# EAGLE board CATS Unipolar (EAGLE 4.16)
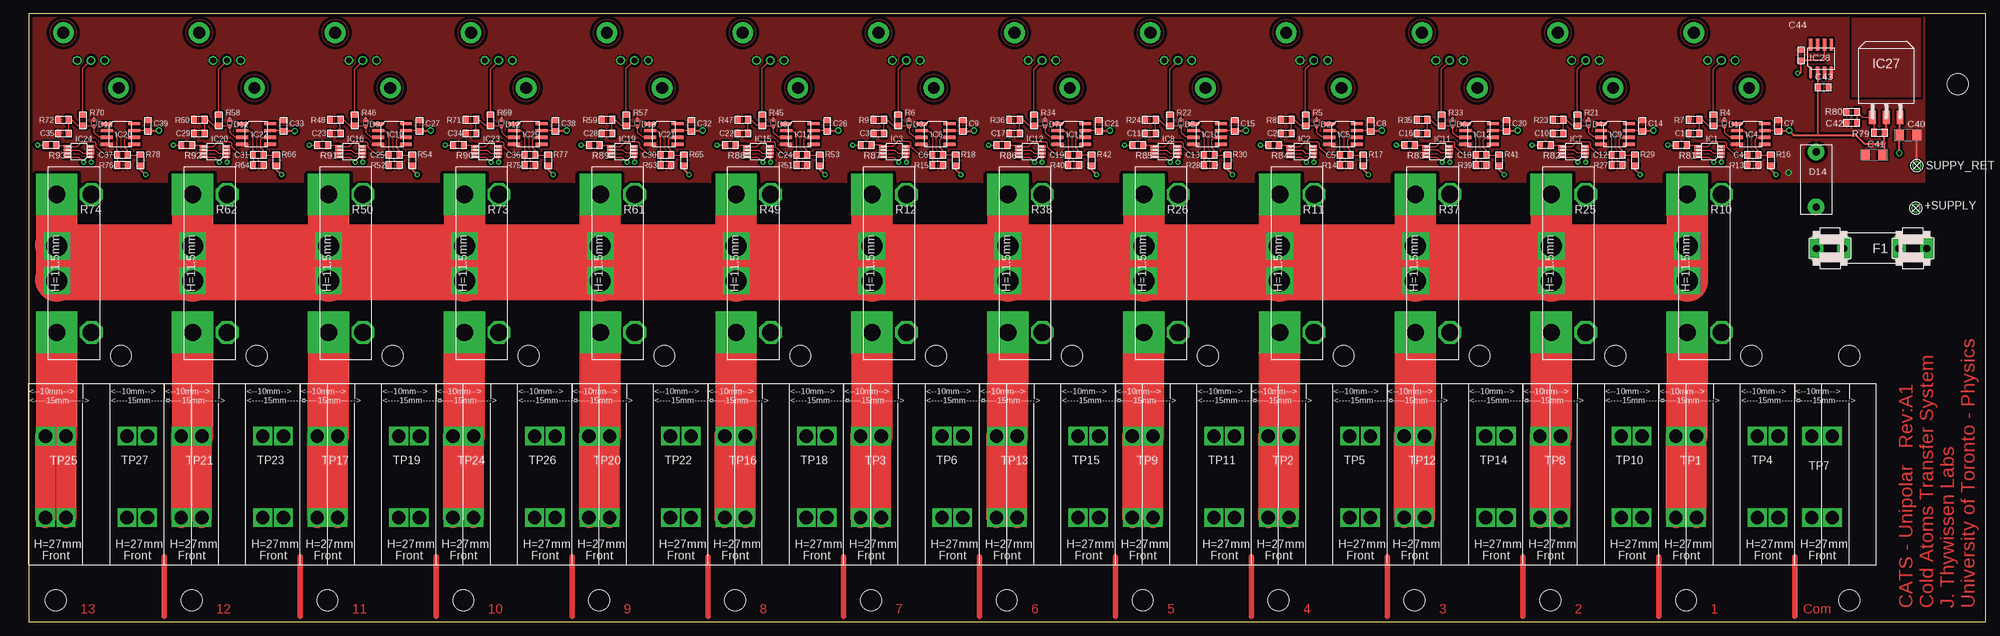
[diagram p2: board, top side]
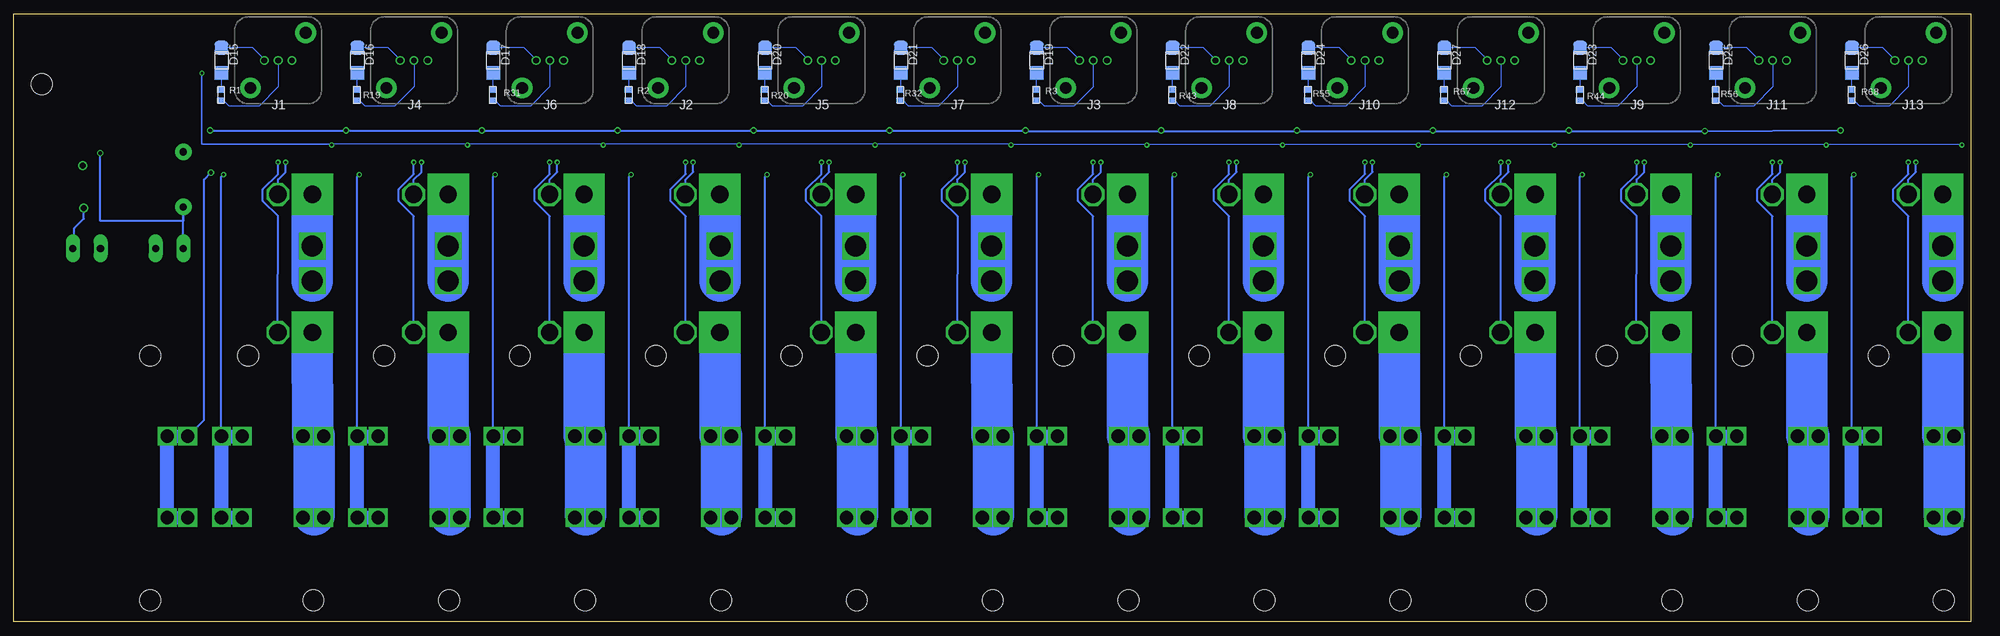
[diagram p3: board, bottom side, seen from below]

Size 360.16 x 112 mm. Coordinates in mm from the lower left corner, seen from the top.
Outline: 0,112 0,0 360.16,0 360.16,112 0,112
Copper layers (1*16): Top 0.035mm / dielectric 1.5mm / Bottom 0.035mm
Design rules "DRC standard check (7mil trace and gap, 20mil drill, etc)": minimum track width 7mil, minimum drill 20mil, track to track 7mil, track to pad 7mil, pad to pad 7mil, via to via 7mil, smd to smd 7mil, copper to edge 25mil, drill to drill 8mil, minimum pad ring 10mil, minimum via ring 8mil, stop-mask expansion 4mil, vias tented up to drill 0mil, thermal gap 10mil
Net classes: 0 default: clearance 0.406 mm; 1 Power: width 1.27 mm, drill 0.178 mm, clearance 3.175 mm
Holes 3.86 mm at 5,4 30,4 55,4 80,4 105,4 130,4 155,4 180,4 205,4 230,4 255,4 280,4 305,4 335,4 355,99 17,49 42,49 67,49 92,49 117,49 142,49 167,49 192,49 217,49 242,49 267,49 292,49 317,49 335,49
bKeepout: area 1.5,0.5 to 8.5,7.5; area 26.5,0.5 to 33.5,7.5; area 51.5,0.5 to 58.5,7.5; area 76.5,0.5 to 83.5,7.5; area 101.5,0.5 to 108.5,7.5; area 126.5,0.5 to 133.5,7.5; area 151.5,0.5 to 158.5,7.5; area 176.5,0.5 to 183.5,7.5; area 201.5,0.5 to 208.5,7.5; area 226.5,0.5 to 233.5,7.5; area 251.5,0.5 to 258.5,7.5; area 276.5,0.5 to 283.5,7.5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
tRestrict: 65 lines

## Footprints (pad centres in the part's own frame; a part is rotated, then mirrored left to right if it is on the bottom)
TP-0.042B = drill 1.067 round: TP 0,0
2012(0805) = smd 1.016 x 1.397: 1 -0.953,0; 2 0.953,0
EIA-A = smd 1.6 x 1.8: 1 -1.27,0; 2 1.905,0
SOD523 = smd 0.7 x 0.5: A 1.27,0; C 0,0
PASSIVE_0.4" = drill 1.321 pad 3.048 round: 1 -5.08,0; 2 5.08,0
1209 = smd 2.5 x 2.5: A 2.3,0; K -2.3,0
FUSE = drill 1.321 pad 2.54 long: 1A -10.16,0; 1B -5.08,0; 2A 10.16,0; 2B 5.08,0
MSOP8 = smd 0.4 x 1.2: 1 -0.635,-1.905; 2 0,-1.905; 3 0.635,-1.905; 4 1.27,-1.905; 5 1.27,2.54; 6 0.635,2.54; 7 0,2.54; 8 -0.635,2.54
SOIC-8 = smd 0.6 x 2.2: 1 -1.27,-2.54; 2 0,-2.54; 3 1.27,-2.54; 4 2.54,-2.54; 5 2.54,2.54; 6 1.27,2.54; 7 0,2.54; 8 -1.27,2.54
TO263 = smd 1.27 x 2.54: 1 -2.54,0; 2 0,0; 3 2.54,0
CONN-BNC-AMP-TYPE1VERT = drill 1.067 round: CONDUCTOR 0,0; SHIELD1 -2.54,0; SHIELD2 2.54,0 | drill 2.184 pad 3.81 round: MTG1 -5.08,-5.08; MTG2 5.08,5.08
OHMITE_650 = drill 3.175 pad 7.62 square: CURRENT1 -12.7,-3.81; CURRENT2 12.7,-3.81 | drill 3.175 octagon: SENSE1 -12.7,2.54; SENSE2 12.7,2.54
PHEONIX_ZFKDS-10/15MM-TERMINAL-BLOCK = drill 2.438 square: T@1 -1.9,-7.5; T@2 1.9,-7.5; T@3 1.9,7.5; T@4 -1.9,7.5

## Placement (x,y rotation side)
+SUPPLY  [TP-0.042B]  347.25,76.2 90 top
C1  10nF  [2012(0805)]  306.43,89.95 0 top
C2  10nF  [2012(0805)]  231.43,89.95 0 top
C3  10nF  [2012(0805)]  156.43,89.95 0 top
C4  100pF  [2012(0805)]  317.27,86.01 0 top
C5  100pF  [2012(0805)]  242.27,86.01 0 top
C6  100pF  [2012(0805)]  167.27,86.01 0 top
C7  0.1uF  [2012(0805)]  321.97,91.35 90 top
C8  0.1uF  [2012(0805)]  246.97,91.35 90 top
C9  0.1uF  [2012(0805)]  171.97,91.35 90 top
C10  10nF  [2012(0805)]  281.43,89.95 0 top
C11  10nF  [2012(0805)]  206.43,89.95 0 top
C12  100pF  [2012(0805)]  292.27,86.01 0 top
C13  100pF  [2012(0805)]  217.27,86.01 0 top
C14  0.1uF  [2012(0805)]  296.97,91.35 90 top
C15  0.1uF  [2012(0805)]  221.97,91.35 90 top
C16  10nF  [2012(0805)]  256.43,89.95 0 top
C17  10nF  [2012(0805)]  181.43,89.95 0 top
C18  100pF  [2012(0805)]  267.27,86.01 0 top
C19  100pF  [2012(0805)]  192.27,86.01 0 top
C20  0.1uF  [2012(0805)]  271.97,91.35 90 top
C21  0.1uF  [2012(0805)]  196.97,91.35 90 top
C22  10nF  [2012(0805)]  131.43,89.95 0 top
C23  10nF  [2012(0805)]  56.43,89.95 0 top
C24  100pF  [2012(0805)]  142.27,86.01 0 top
C25  100pF  [2012(0805)]  67.27,86.01 0 top
C26  0.1uF  [2012(0805)]  146.97,91.35 90 top
C27  0.1uF  [2012(0805)]  71.97,91.35 90 top
C28  10nF  [2012(0805)]  106.43,89.95 0 top
C29  10nF  [2012(0805)]  31.43,89.95 0 top
C30  100pF  [2012(0805)]  117.27,86.01 0 top
C31  100pF  [2012(0805)]  42.27,86.01 0 top
C32  0.1uF  [2012(0805)]  121.97,91.35 90 top
C33  0.1uF  [2012(0805)]  46.97,91.35 90 top
C34  10nF  [2012(0805)]  81.43,89.95 0 top
C35  10nF  [2012(0805)]  6.43,89.95 0 top
C36  100pF  [2012(0805)]  92.27,86.01 0 top
C37  100pF  [2012(0805)]  17.27,86.01 0 top
C38  0.1uF  [2012(0805)]  96.97,91.35 90 top
C39  0.1uF  [2012(0805)]  21.97,91.35 90 top
C40  100uF/35V  [EIA-A]  346.14,89.6 180 top
C41  100uF/35V  [EIA-A]  339.28,86.04 0 top
C42  0.1uF  [2012(0805)]  335.47,91.88 0 top
C43  0.1uF  [2012(0805)]  330.22,98.42 0 top
C44  0.1uF  [2012(0805)]  326.14,104.33 270 top
D1  1N4148WT  [SOD523]  312.02,91.22 90 top
D2  1N4148WT  [SOD523]  237.02,91.22 90 top
D3  1N4148WT  [SOD523]  162.02,91.22 90 top
D4  1N4148WT  [SOD523]  287.02,91.22 90 top
D5  1N4148WT  [SOD523]  212.02,91.22 90 top
D6  1N4148WT  [SOD523]  262.02,91.22 90 top
D7  1N4148WT  [SOD523]  187.02,91.22 90 top
D8  1N4148WT  [SOD523]  137.02,91.22 90 top
D9  1N4148WT  [SOD523]  62.02,91.22 90 top
D10  1N4148WT  [SOD523]  112.02,91.22 90 top
D11  1N4148WT  [SOD523]  37.02,91.22 90 top
D12  1N4148WT  [SOD523]  87.02,91.22 90 top
D13  1N4148WT  [SOD523]  12.02,91.22 90 top
D14  1N4750A  [PASSIVE_0.4"]  328.93,81.47 270 top
D15  SML-LXL1209UPGC  [1209]  321.9,103.4 270 bottom
D16  SML-LXL1209UPGC  [1209]  296.9,103.4 270 bottom
D17  SML-LXL1209UPGC  [1209]  271.9,103.4 270 bottom
D18  SML-LXL1209UPGC  [1209]  246.9,103.4 270 bottom
D19  SML-LXL1209UPGC  [1209]  171.9,103.4 270 bottom
D20  SML-LXL1209UPGC  [1209]  221.9,103.4 270 bottom
D21  SML-LXL1209UPGC  [1209]  196.9,103.4 270 bottom
D22  SML-LXL1209UPGC  [1209]  146.9,103.4 270 bottom
D23  SML-LXL1209UPGC  [1209]  71.9,103.4 270 bottom
D24  SML-LXL1209UPGC  [1209]  121.9,103.4 270 bottom
D25  SML-LXL1209UPGC  [1209]  46.9,103.4 270 bottom
D26  SML-LXL1209UPGC  [1209]  21.9,103.4 270 bottom
D27  SML-LXL1209UPGC  [1209]  96.9,103.4 270 bottom
F1  0.1A-5x20  [FUSE]  339.09,68.77 180 top
IC1  AD8212RMZ  [MSOP8]  309.61,86.27 90 top
IC2  AD8212RMZ  [MSOP8]  234.6,86.27 90 top
IC3  AD8212RMZ  [MSOP8]  159.6,86.27 90 top
IC4  AD820ARZ  [SOIC-8]  316.89,90.46 270 top
IC5  AD820ARZ  [SOIC-8]  241.89,90.46 270 top
IC6  AD820ARZ  [SOIC-8]  166.89,90.46 270 top
IC7  AD8212RMZ  [MSOP8]  284.61,86.27 90 top
IC8  AD8212RMZ  [MSOP8]  209.6,86.27 90 top
IC9  AD820ARZ  [SOIC-8]  291.89,90.46 270 top
IC10  AD820ARZ  [SOIC-8]  216.89,90.46 270 top
IC11  AD8212RMZ  [MSOP8]  259.61,86.27 90 top
IC12  AD8212RMZ  [MSOP8]  184.6,86.27 90 top
IC13  AD820ARZ  [SOIC-8]  266.89,90.46 270 top
IC14  AD820ARZ  [SOIC-8]  191.89,90.46 270 top
IC15  AD8212RMZ  [MSOP8]  134.6,86.27 90 top
IC16  AD8212RMZ  [MSOP8]  59.6,86.27 90 top
IC17  AD820ARZ  [SOIC-8]  141.89,90.46 270 top
IC18  AD820ARZ  [SOIC-8]  66.89,90.46 270 top
IC19  AD8212RMZ  [MSOP8]  109.61,86.27 90 top
IC20  AD8212RMZ  [MSOP8]  34.6,86.27 90 top
IC21  AD820ARZ  [SOIC-8]  116.89,90.46 270 top
IC22  AD820ARZ  [SOIC-8]  41.89,90.46 270 top
IC23  AD8212RMZ  [MSOP8]  84.61,86.27 90 top
IC24  AD8212RMZ  [MSOP8]  9.61,86.27 90 top
IC25  AD820ARZ  [SOIC-8]  91.89,90.46 270 top
IC26  AD820ARZ  [SOIC-8]  16.89,90.46 270 top
IC27  LM1086CS-ADJ  [TO263]  341.82,92.9 0 top
IC28  ADR435AR(Z)  [SOIC-8]  329.18,103.69 0 top
J1  Amp 227673-1  [CONN-BNC-AMP-TYPE1VERT]  311.49,103.38 0 bottom
J2  Amp 227673-1  [CONN-BNC-AMP-TYPE1VERT]  236.49,103.38 0 bottom
J3  Amp 227673-1  [CONN-BNC-AMP-TYPE1VERT]  161.49,103.38 0 bottom
J4  Amp 227673-1  [CONN-BNC-AMP-TYPE1VERT]  286.49,103.38 0 bottom
J5  Amp 227673-1  [CONN-BNC-AMP-TYPE1VERT]  211.49,103.38 0 bottom
J6  Amp 227673-1  [CONN-BNC-AMP-TYPE1VERT]  261.49,103.38 0 bottom
J7  Amp 227673-1  [CONN-BNC-AMP-TYPE1VERT]  186.49,103.38 0 bottom
J8  Amp 227673-1  [CONN-BNC-AMP-TYPE1VERT]  136.49,103.38 0 bottom
J9  Amp 227673-1  [CONN-BNC-AMP-TYPE1VERT]  61.49,103.38 0 bottom
J10  Amp 227673-1  [CONN-BNC-AMP-TYPE1VERT]  111.49,103.38 0 bottom
J11  Amp 227673-1  [CONN-BNC-AMP-TYPE1VERT]  36.49,103.38 0 bottom
J12  Amp 227673-1  [CONN-BNC-AMP-TYPE1VERT]  86.49,103.38 0 bottom
J13  Amp 227673-1  [CONN-BNC-AMP-TYPE1VERT]  11.49,103.38 0 bottom
R1  3.01K  [2012(0805)]  322,97 270 bottom
R2  3.01K  [2012(0805)]  247,97 270 bottom
R3  3.01K  [2012(0805)]  172,97 270 bottom
R4  9.09K  [2012(0805)]  309.99,92.36 270 top
R5  9.09K  [2012(0805)]  234.99,92.36 270 top
R6  9.09K  [2012(0805)]  159.99,92.36 270 top
R7  1K  [2012(0805)]  306.43,92.49 0 top
R8  1K  [2012(0805)]  231.43,92.49 0 top
R9  1K  [2012(0805)]  156.43,92.49 0 top
R10  2mOhm/5W  [OHMITE_650]  309,66 270 top
R11  2mOhm/5W  [OHMITE_650]  234,66 270 top
R12  2mOhm/5W  [OHMITE_650]  159,66 270 top
R13  3.92K  [2012(0805)]  317.27,84.11 180 top
R14  3.92K  [2012(0805)]  242.27,84.11 180 top
R15  3.92K  [2012(0805)]  167.27,84.11 180 top
R16  100  [2012(0805)]  320.57,85 270 top
R17  100  [2012(0805)]  245.57,85 270 top
R18  100  [2012(0805)]  170.57,85 270 top
R19  3.01K  [2012(0805)]  297,97 270 bottom
R20  3.01K  [2012(0805)]  222,97 270 bottom
R21  9.09K  [2012(0805)]  284.99,92.36 270 top
R22  9.09K  [2012(0805)]  209.99,92.36 270 top
R23  1K  [2012(0805)]  281.43,92.49 0 top
R24  1K  [2012(0805)]  206.43,92.49 0 top
R25  2mOhm/5W  [OHMITE_650]  284,66 270 top
R26  2mOhm/5W  [OHMITE_650]  209,66 270 top
R27  3.92K  [2012(0805)]  292.27,84.11 180 top
R28  3.92K  [2012(0805)]  217.27,84.11 180 top
R29  100  [2012(0805)]  295.57,85 270 top
R30  100  [2012(0805)]  220.57,85 270 top
R31  3.01K  [2012(0805)]  272,97 270 bottom
R32  3.01K  [2012(0805)]  197,97 270 bottom
R33  9.09K  [2012(0805)]  259.99,92.36 270 top
R34  9.09K  [2012(0805)]  184.99,92.36 270 top
R35  1K  [2012(0805)]  256.43,92.49 0 top
R36  1K  [2012(0805)]  181.43,92.49 0 top
R37  2mOhm/5W  [OHMITE_650]  259,66 270 top
R38  2mOhm/5W  [OHMITE_650]  184,66 270 top
R39  3.92K  [2012(0805)]  267.27,84.11 180 top
R40  3.92K  [2012(0805)]  192.27,84.11 180 top
R41  100  [2012(0805)]  270.57,85 270 top
R42  100  [2012(0805)]  195.57,85 270 top
R43  3.01K  [2012(0805)]  147,97 270 bottom
R44  3.01K  [2012(0805)]  72,97 270 bottom
R45  9.09K  [2012(0805)]  134.99,92.36 270 top
R46  9.09K  [2012(0805)]  59.99,92.36 270 top
R47  1K  [2012(0805)]  131.43,92.49 0 top
R48  1K  [2012(0805)]  56.43,92.49 0 top
R49  2mOhm/5W  [OHMITE_650]  134,66 270 top
R50  2mOhm/5W  [OHMITE_650]  59,66 270 top
R51  3.92K  [2012(0805)]  142.27,84.11 180 top
R52  3.92K  [2012(0805)]  67.27,84.11 180 top
R53  100  [2012(0805)]  145.57,85 270 top
R54  100  [2012(0805)]  70.57,85 270 top
R55  3.01K  [2012(0805)]  122,97 270 bottom
R56  3.01K  [2012(0805)]  47,97 270 bottom
R57  9.09K  [2012(0805)]  109.99,92.36 270 top
R58  9.09K  [2012(0805)]  34.99,92.36 270 top
R59  1K  [2012(0805)]  106.43,92.49 0 top
R60  1K  [2012(0805)]  31.43,92.49 0 top
R61  2mOhm/5W  [OHMITE_650]  109,66 270 top
R62  2mOhm/5W  [OHMITE_650]  34,66 270 top
R63  3.92K  [2012(0805)]  117.27,84.11 180 top
R64  3.92K  [2012(0805)]  42.27,84.11 180 top
R65  100  [2012(0805)]  120.57,85 270 top
R66  100  [2012(0805)]  45.57,85 270 top
R67  3.01K  [2012(0805)]  97,97 270 bottom
R68  3.01K  [2012(0805)]  22,97 270 bottom
R69  9.09K  [2012(0805)]  84.99,92.36 270 top
R70  9.09K  [2012(0805)]  9.99,92.36 270 top
R71  1K  [2012(0805)]  81.43,92.49 0 top
R72  1K  [2012(0805)]  6.43,92.49 0 top
R73  2mOhm/5W  [OHMITE_650]  84,66 270 top
R74  2mOhm/5W  [OHMITE_650]  9,66 270 top
R75  3.92K  [2012(0805)]  92.27,84.11 180 top
R76  3.92K  [2012(0805)]  17.27,84.11 180 top
R77  100  [2012(0805)]  95.57,85 270 top
R78  100  [2012(0805)]  20.57,85 270 top
R79  124  [2012(0805)]  340.55,90.11 0 top
R80  1.47K  [2012(0805)]  335.47,93.92 0 top
R81  75K  [2012(0805)]  304.12,87.76 180 top
R82  75K  [2012(0805)]  279.12,87.76 180 top
R83  75K  [2012(0805)]  254.12,87.76 180 top
R84  75K  [2012(0805)]  229.12,87.76 180 top
R85  75K  [2012(0805)]  204.12,87.76 180 top
R86  75K  [2012(0805)]  179.12,87.76 180 top
R87  75K  [2012(0805)]  154.12,87.76 180 top
R88  75K  [2012(0805)]  129.12,87.76 180 top
R89  75K  [2012(0805)]  104.12,87.76 180 top
R90  75K  [2012(0805)]  79.12,87.76 180 top
R91  75K  [2012(0805)]  54.12,87.76 180 top
R92  75K  [2012(0805)]  29.12,87.76 180 top
R93  75K  [2012(0805)]  4.12,87.76 180 top
SUPPY_RET  [TP-0.042B]  347.44,84.01 270 top
TP1  Pheonix-1987631  [PHEONIX_ZFKDS-10/15MM-TERMINAL-BLOCK]  305,26.7 0 top
TP2  Pheonix-1987631  [PHEONIX_ZFKDS-10/15MM-TERMINAL-BLOCK]  230,26.7 0 top
TP3  Pheonix-1987631  [PHEONIX_ZFKDS-10/15MM-TERMINAL-BLOCK]  155,26.7 0 top
TP4  Pheonix-1987628  [PHEONIX_ZFKDS-10/15MM-TERMINAL-BLOCK]  320,26.7 0 top
TP5  Pheonix-1987628  [PHEONIX_ZFKDS-10/15MM-TERMINAL-BLOCK]  245,26.7 0 top
TP6  Pheonix-1987628  [PHEONIX_ZFKDS-10/15MM-TERMINAL-BLOCK]  170,26.7 0 top
TP7  Pheonix-1987628  [PHEONIX_ZFKDS-10/15MM-TERMINAL-BLOCK]  330,26.7 0 top
TP8  Pheonix-1987631  [PHEONIX_ZFKDS-10/15MM-TERMINAL-BLOCK]  280,26.7 0 top
TP9  Pheonix-1987631  [PHEONIX_ZFKDS-10/15MM-TERMINAL-BLOCK]  205,26.7 0 top
TP10  Pheonix-1987628  [PHEONIX_ZFKDS-10/15MM-TERMINAL-BLOCK]  295,26.7 0 top
TP11  Pheonix-1987628  [PHEONIX_ZFKDS-10/15MM-TERMINAL-BLOCK]  220,26.7 0 top
TP12  Pheonix-1987631  [PHEONIX_ZFKDS-10/15MM-TERMINAL-BLOCK]  255,26.7 0 top
TP13  Pheonix-1987631  [PHEONIX_ZFKDS-10/15MM-TERMINAL-BLOCK]  180,26.7 0 top
TP14  Pheonix-1987628  [PHEONIX_ZFKDS-10/15MM-TERMINAL-BLOCK]  270,26.7 0 top
TP15  Pheonix-1987628  [PHEONIX_ZFKDS-10/15MM-TERMINAL-BLOCK]  195,26.7 0 top
TP16  Pheonix-1987631  [PHEONIX_ZFKDS-10/15MM-TERMINAL-BLOCK]  130,26.7 0 top
TP17  Pheonix-1987631  [PHEONIX_ZFKDS-10/15MM-TERMINAL-BLOCK]  55,26.7 0 top
TP18  Pheonix-1987628  [PHEONIX_ZFKDS-10/15MM-TERMINAL-BLOCK]  145,26.7 0 top
TP19  Pheonix-1987628  [PHEONIX_ZFKDS-10/15MM-TERMINAL-BLOCK]  70,26.7 0 top
TP20  Pheonix-1987631  [PHEONIX_ZFKDS-10/15MM-TERMINAL-BLOCK]  105,26.7 0 top
TP21  Pheonix-1987631  [PHEONIX_ZFKDS-10/15MM-TERMINAL-BLOCK]  30,26.7 0 top
TP22  Pheonix-1987628  [PHEONIX_ZFKDS-10/15MM-TERMINAL-BLOCK]  120,26.7 0 top
TP23  Pheonix-1987628  [PHEONIX_ZFKDS-10/15MM-TERMINAL-BLOCK]  45,26.7 0 top
TP24  Pheonix-1987631  [PHEONIX_ZFKDS-10/15MM-TERMINAL-BLOCK]  80,26.7 0 top
TP25  Pheonix-1987631  [PHEONIX_ZFKDS-10/15MM-TERMINAL-BLOCK]  5,26.7 0 top
TP26  Pheonix-1987628  [PHEONIX_ZFKDS-10/15MM-TERMINAL-BLOCK]  95,26.7 0 top
TP27  Pheonix-1987628  [PHEONIX_ZFKDS-10/15MM-TERMINAL-BLOCK]  20,26.7 0 top
U$106  [TITLEBLOCK_PCB]  not placed on the board

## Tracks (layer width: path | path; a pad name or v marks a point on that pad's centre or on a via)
+5.0V  (via drill 0.51)
  Top 0.178: R93.2 3.17,87.82 v1.65,87.82 | v26.65,87.82 26.65,87.75 R92.2 | v51.65,87.82 51.65,87.75 R91.2 | v76.65,87.82 76.65,87.75 R90.2 | v101.65,87.82 101.65,87.75 R89.2 | v126.65,87.82 126.65,87.75 R88.2 | v151.65,87.82 151.65,87.75 R87.2 | v176.65,87.82 176.65,87.75 R86.2 | v201.65,87.82 201.65,87.75 R85.2 | v226.65,87.82 226.65,87.75 R84.2 | v251.65,87.82 251.65,87.75 R83.2 | v276.65,87.82 276.65,87.75 R82.2 | v301.65,87.82 301.65,87.75 R81.2
  Top 0.254: 326.14,103.44 C44.2 | IC28.6 330.45,103.44 326.14,103.44 | v325.5,101.03 326.14,101.03 326.14,103.44
  Bottom 0.178: 276.65,88 v276.65,87.82 | v301.65,87.82 301.65,88 276.65,88 | 251.65,88 v251.65,87.82 | 251.65,88 276.65,88 | 226.65,88 v226.65,87.82 | 226.65,88 251.65,88 | 201.65,88 v201.65,87.82 | 201.65,88 226.65,88 | v176.65,87.82 176.65,88 | 176.65,88 201.65,88 | 151.65,88 v151.65,87.82 | 176.65,88 151.65,88 | 126.65,88 v126.65,87.82 | 151.65,88 126.65,88 | 101.65,88 v101.65,87.82 | 126.65,88 101.65,88 | 76.65,88 v76.65,87.82 | 101.65,88 76.65,88 | 51.65,88 v51.65,87.82 | 76.65,88 51.65,88 | 26.65,88 v26.65,87.82 | 51.65,88 26.65,88 | 1.65,88 1.5,88 | 1.65,88 v1.65,87.82 | 26.65,88 1.65,88
  Bottom 0.254: v325.5,101.03 325.5,87.95 301.62,87.95 301.62,88 301.65,88
+16V  (via drill 0.71)
  Top 0.178: C39.1 22.05,90.39 22.05,90.33 21.92,90.46 IC26.7 | C33.1 47.05,90.39 47.05,90.33 46.92,90.46 IC22.7 | C27.1 72.05,90.39 72.05,90.33 71.92,90.46 IC18.7 | C38.1 97.05,90.39 97.05,90.33 96.92,90.46 IC25.7 | C32.1 122.05,90.39 122.05,90.33 121.92,90.46 IC21.7 | C26.1 147.05,90.39 147.05,90.33 146.92,90.46 IC17.7 | C9.1 172.05,90.39 172.05,90.33 171.92,90.46 IC6.7 | C21.1 197.05,90.39 197.05,90.33 196.92,90.46 IC14.7 | C15.1 222.05,90.39 222.05,90.33 221.92,90.46 IC10.7 | C8.1 247.05,90.39 247.05,90.33 246.92,90.46 IC5.7 | C20.1 272.05,90.39 272.05,90.33 271.92,90.46 IC13.7 | C14.1 297.05,90.39 297.05,90.33 296.92,90.46 IC9.7 | C7.1 322.05,90.39 322.05,90.33 321.92,90.46 IC4.7
  Top 0.254: 329.18,98.42 329.18,98.36 | 329.18,98.42 C43.1 329.27,89.6 329.31,89.6 | 329.18,98.42 IC28.2
  Top 0.381: 22.05,90.39 24,90.39 v24,90.5 | v49,90.39 47.05,90.39 | 72.05,90.39 74,90.39 v74,90.5 | 97.05,90.39 99,90.39 v99,90.5 | 122.05,90.39 124,90.39 v124,90.5 | 147.05,90.39 149,90.39 v149,90.5 | 172.05,90.39 174,90.39 v174,90.5 | 197.05,90.39 199,90.39 v199,90.5 | 222.05,90.39 224,90.39 v224,90.5 | 247.05,90.39 249,90.39 v249,90.5 | 272.05,90.39 274,90.39 v274,90.5 | 297.05,90.39 299,90.39 v299,90.5 | 324,90.39 322.05,90.39 | v324,90.5 324,90.39 | IC27.2 341.82,90.11 R79.2 341.5,88.07 | 341.5,88.07 341.5,86.04 C41.2 | 324,90.39 324.8,89.6 329.31,89.6 336.23,89.6 337.76,88.07 341.5,88.07 | 341.5,88.07 341.57,88.07
  Bottom 0.254: 49,90.37 v49,90.39
  Bottom 0.381: 49,90.37 v24,90.5 | 74,90.39 v49,90.39 | 74,90.39 v74,90.5 | 99,90.39 74,90.39 | 99,90.39 v99,90.5 | 124,90.39 99,90.39 | 124,90.39 v124,90.5 | 149,90.39 124,90.39 | 149,90.39 v149,90.5 | 174,90.39 149,90.39 | v174,90.5 174,90.39 | 174,90.39 199,90.39 | 199,90.39 v199,90.5 | 199,90.39 224,90.39 | 224,90.39 v224,90.5 | 224,90.39 249,90.39 | 249,90.39 v249,90.5 | 249,90.39 274,90.39 | 274,90.39 v274,90.5 | 274,90.39 299,90.39 | 299,90.39 v299,90.5 | 299,90.39 324,90.39 v324,90.5
  pour Top (isolate 0.508): 335.47,111.14 335.47,96.71 348.17,96.71 348.17,111.14
+V-COIL  (via drill 3.86)
  Top 2: 5,69.4 5,69.3 5.2,64.1
  Top 7.62: R74.CURRENT1 v5.2,69.2 5.2,64.1 v5.2,62.8 5,63 30,63 | 55,63 30,63 | 80,63 55,63 | 105,63 80,63 | 130,63 105,63 | 155,63 130,63 | 180,63 155,63 | 180,63 205,63 | 205,63 230,63 | 230,63 255,63 | 255,63 280,63 | 280,63 305,63 v305.2,62.8 v305.2,69.2 R10.CURRENT1 | 30,63 v30.2,62.8 v30.2,69.2 R62.CURRENT1 | 55,63 v55.2,62.8 v55.2,69.2 R50.CURRENT1 | 80,63 v80.2,62.8 v80.2,69.2 R73.CURRENT1 | 105,63 v105.2,62.8 v105.2,69.2 R61.CURRENT1 | 130,63 v130.2,62.8 v130.2,69.2 R49.CURRENT1 | 155,63 v155.2,62.8 v155.2,69.2 R12.CURRENT1 | 180,63 v180.2,62.8 v180.2,69.2 R38.CURRENT1 | 205,63 v205.2,62.8 v205.2,69.2 R26.CURRENT1 | 230,63 v230.2,62.8 v230.2,69.2 R11.CURRENT1 | 255,63 v255.2,62.8 v255.2,69.2 R37.CURRENT1 | 280,63 v280.2,62.8 v280.2,69.2 R25.CURRENT1 | 5,69.4 305,69.4
  Bottom 7.62: v5.2,62.8 v5.2,69.2 R74.CURRENT1 | R62.CURRENT1 v30.2,69.2 v30.2,62.8 | R50.CURRENT1 v55.2,69.2 v55.2,62.8 | R73.CURRENT1 v80.2,69.2 v80.2,62.8 | R61.CURRENT1 v105.2,69.2 v105.2,62.8 | R49.CURRENT1 v130.2,69.2 v130.2,62.8 | R12.CURRENT1 v155.2,69.2 v155.2,62.8 | R38.CURRENT1 v180.2,69.2 v180.2,62.8 | R26.CURRENT1 v205.2,69.2 v205.2,62.8 | R11.CURRENT1 v230.2,69.2 v230.2,62.8 | R37.CURRENT1 v255.2,69.2 v255.2,62.8 | R25.CURRENT1 v280.2,69.2 v280.2,62.8 | R10.CURRENT1 v305.2,69.2 v305.2,62.8
AGND  (via drill 0.71)
  Top 0.36: C40.1 347.44,89.56 SUPPY_RET.TP
  Bottom 0.18: J13.SHIELD1 14.03,103.5 14,103.5 16.2,105.7 D26.K | J11.SHIELD1 39.03,103.5 39,103.5 41.2,105.7 D25.K | J9.SHIELD1 64.03,103.5 64,103.5 66.2,105.7 D23.K | J12.SHIELD1 89.03,103.5 89,103.5 91.2,105.7 D27.K | J10.SHIELD1 114.03,103.5 114,103.5 116.2,105.7 D24.K | J8.SHIELD1 139.03,103.5 139,103.5 141.2,105.7 D22.K | J3.SHIELD1 164.03,103.5 164,103.5 166.2,105.7 D19.K | J7.SHIELD1 189.03,103.5 189,103.5 191.2,105.7 D21.K | J5.SHIELD1 214.03,103.5 214,103.5 216.2,105.7 D20.K | J2.SHIELD1 239.03,103.5 239,103.5 241.2,105.7 D18.K | J6.SHIELD1 264.03,103.5 264,103.5 266.2,105.7 D17.K | J4.SHIELD1 289.03,103.5 289,103.5 291.2,105.7 D16.K | J1.SHIELD1 314.03,103.5 314,103.5 316.2,105.7 D15.K
  Bottom 0.381: TP7.T@4 325.12,37.18 325.12,81.47 v323.85,82.74
  Bottom 2.54: TP7.T@1 331.85,19.11 TP7.T@2 331.85,34.23 TP7.T@3 328.17,34.23 TP7.T@4
  pour Top (isolate 0.178, rank 2): 0,112 0,81 349,81 349,112
N$1
  Top 0.18: J13.CONDUCTOR 11.49,103.5 11.5,103.5 9.99,101.99 R70.1
  Bottom 0.18: R68.2 21.55,96.05 20.5,95 15,95 11.5,98.5 11.5,103.5 11.49,103.5 J13.CONDUCTOR
N$2
  Top 0.178: 7.45,89.95 C35.2 R72.2 7.95,92.49 8.97,91.47 9.86,91.47 9.99,91.35 R70.2 11.7,91.41 12.02,91.09 | 12.02,91.09 D13.C | 12.02,91.09 12.02,90.2 12.91,89.31 14.3,89.31 14.43,89.19 IC26.3
N$3  (via drill 0.51)
  Top 0.178: v11.51,84.62 IC24.1
  Bottom 0.381: R74.SENSE2 11.51,74.71 14.3,77.5 14.3,79.66 11.51,82.46 v11.51,84.62
N$4  (via drill 0.51)
  Top 0.178: v10.11,84.62 9.22,85.5 7.32,85.5 7.19,85.63 IC24.8
  Bottom 0.381: R74.SENSE1 11.51,81.44 10.11,82.84 v10.11,84.62
N$5
  Top 0.178: IC24.6 9.35,86.9 9.99,86.27 IC24.2
N$6
  Top 0.178: R76.2 16.32,86 16.34,86.01 | 14.43,90.33 14.3,90.46 IC26.2 14.43,90.46 14.3,90.33 15.7,90.33 16.34,89.7 16.34,86.01 | 16.34,86.01 C37.1 14.05,86.01 12.78,87.16 12.4,87.54 12.4,88.17 12.14,88.43 9.86,88.43 8.97,87.54 IC24.5 7.07,87.69 5.07,87.69 R93.1
N$7
  Top 0.178: 19.51,89.19 IC26.6 18.11,89.19 17.73,88.81 17.73,87.28 18.22,86.79 C37.2 18.11,86.01 18.18,85.95 R78.1
N$8
  Top 3.81: 6.81,34.2 TP25.T@3 | TP25.T@2 6.9,34.11 6.81,34.2 | TP25.T@4 3.1,34.32 3.13,34.32 3.1,34.3 TP25.T@4 | TP25.T@1 TP25.T@4 | TP25.T@4 3.1,34.07 3.13,34.07 3.25,34.2 6.81,34.2
  Top 7.62: R74.CURRENT2 5.16,34.32
  Bottom 2.54: 5.29,34.45 5.16,34.45 | 4.87,34.23 5.07,34.23 5.29,34.45 | 5.29,34.45 5.03,34.2 6.81,34.2 TP25.T@3
  Bottom 7.62: R74.CURRENT2 5.16,34.45 5.16,34.32 | 4.87,34.23 4.87,19.71
N$9
  Top 0.18: J11.CONDUCTOR 36.49,103.25 36.5,103.25 34.99,101.74 34.99,94.75 R58.1
  Bottom 0.18: R56.2 46.55,96.05 45.5,95 40,95 36.5,98.5 36.5,103 36.49,103 J11.CONDUCTOR
N$10  (via drill 0.51)
  Top 0.254: R78.2 20.57,83.3 v21.54,82.33
  Bottom 0.254: TP27.T@2 21.8,19.2 21.8,19.21 21.79,19.2 | TP27.T@3 21.8,34.2 21.9,34.09 | TP27.T@3 21.54,34.2 21.42,34.07 21.29,34.2 | 21.92,34.07 21.9,34.07 TP27.T@3
  Bottom 0.381: v21.54,82.33 21.92,81.95 21.92,34.07
  Bottom 2.54: TP27.T@1 21.79,19.2 | TP27.T@2 21.9,34.09 | 21.29,34.2 TP27.T@4
N$11
  Top 0.178: 32.45,89.95 C29.2 R60.2 32.95,92.49 33.97,91.47 34.86,91.47 34.99,91.35 R58.2 36.7,91.41 37.02,91.09 | 37.02,91.09 D11.C | 37.02,91.09 37.02,90.2 37.91,89.31 39.3,89.31 39.43,89.19 IC22.3
N$12  (via drill 0.51)
  Top 0.178: v36.51,84.62 IC20.1
  Bottom 0.381: R62.SENSE2 36.51,74.71 39.3,77.5 39.3,79.66 36.51,82.46 v36.51,84.62
N$13  (via drill 0.51)
  Top 0.178: v35.11,84.62 34.22,85.5 32.32,85.5 32.19,85.63 IC20.8
  Bottom 0.381: R62.SENSE1 36.51,81.44 35.11,82.84 v35.11,84.62
N$14
  Top 0.178: IC20.6 34.35,86.9 34.99,86.27 IC20.2
N$15
  Top 0.178: R64.2 41.32,86 41.34,86.01 | 39.43,90.33 39.3,90.46 IC22.2 39.43,90.46 39.3,90.33 40.7,90.33 41.34,89.7 41.34,86.01 | 41.34,86.01 C31.1 39.05,86.01 37.78,87.16 37.4,87.54 37.4,88.17 37.15,88.43 34.86,88.43 33.97,87.54 IC20.5 32.06,87.82 30.07,87.82 R92.1
N$16
  Top 0.178: 44.51,89.19 IC22.6 43.11,89.19 42.73,88.81 42.73,87.28 43.22,86.79 C31.2 43.11,86.01 43.18,85.95 R66.1
N$17
  Top 3.81: 31.81,34.2 TP21.T@3 | TP21.T@2 31.9,34.11 31.81,34.2 | TP21.T@4 28.1,34.32 28.13,34.32 28.1,34.3 TP21.T@4 | TP21.T@1 TP21.T@4 | TP21.T@4 28.1,34.07 28.13,34.07 28.25,34.2 31.81,34.2
  Top 7.62: R62.CURRENT2 30.16,34.32
  Bottom 2.54: 30.29,34.45 30.16,34.45 | 29.87,34.23 30.07,34.23 30.29,34.45 | 30.29,34.45 30.03,34.2 31.81,34.2 TP21.T@3
  Bottom 7.62: R62.CURRENT2 30.16,34.45 30.16,34.32 | 29.87,34.23 29.87,19.71
N$18  (via drill 0.51)
  Top 0.254: R66.2 45.57,83.3 v46.54,82.33
  Bottom 0.254: TP23.T@2 46.8,19.2 46.8,19.21 46.79,19.2 | TP23.T@3 46.8,34.2 46.9,34.09 | TP23.T@3 46.54,34.2 46.42,34.07 46.29,34.2 | 46.92,34.07 46.9,34.07 TP23.T@3
  Bottom 0.381: v46.54,82.33 46.92,81.95 46.92,34.07
  Bottom 2.54: TP23.T@1 46.79,19.2 | TP23.T@2 46.9,34.09 | 46.29,34.2 TP23.T@4
N$19
  Top 0.18: J9.CONDUCTOR 61.49,103.25 61.5,103.25 59.99,101.74 59.99,94.75 R46.1
  Bottom 0.18: R44.2 71.55,96.05 70.5,95 65,95 61.5,98.5 61.5,103 61.49,103 J9.CONDUCTOR
N$20
  Top 0.178: 57.45,89.95 C23.2 R48.2 57.95,92.49 58.97,91.47 59.86,91.47 59.99,91.35 R46.2 61.7,91.41 62.02,91.09 | 62.02,91.09 D9.C | 62.02,91.09 62.02,90.2 62.91,89.31 64.3,89.31 64.43,89.19 IC18.3
N$21  (via drill 0.51)
  Top 0.178: v61.51,84.62 IC16.1
  Bottom 0.381: R50.SENSE2 61.51,74.71 64.3,77.5 64.3,79.66 61.51,82.46 v61.51,84.62
N$22  (via drill 0.51)
  Top 0.178: v60.11,84.62 59.22,85.5 57.32,85.5 57.19,85.63 IC16.8
  Bottom 0.381: R50.SENSE1 61.51,81.44 60.11,82.84 v60.11,84.62
N$23
  Top 0.178: IC16.6 59.35,86.9 59.99,86.27 IC16.2
N$24
  Top 0.178: R52.2 66.32,86 66.34,86.01 | 64.43,90.33 64.3,90.46 IC18.2 64.43,90.46 64.3,90.33 65.7,90.33 66.34,89.7 66.34,86.01 | 66.34,86.01 C25.1 64.05,86.01 62.78,87.16 62.4,87.54 62.4,88.17 62.15,88.43 59.86,88.43 58.97,87.54 IC16.5 57.06,87.82 55.07,87.82 R91.1
N$25
  Top 0.178: 69.51,89.19 IC18.6 68.11,89.19 67.73,88.81 67.73,87.28 68.22,86.79 C25.2 68.11,86.01 68.18,85.95 R54.1
N$26
  Top 3.81: 56.81,34.2 TP17.T@3 | TP17.T@2 56.9,34.11 56.81,34.2 | TP17.T@4 53.1,34.32 53.13,34.32 53.1,34.3 TP17.T@4 | TP17.T@1 TP17.T@4 | TP17.T@4 53.1,34.07 53.13,34.07 53.26,34.2 56.81,34.2
  Top 7.62: R50.CURRENT2 55.16,34.32
  Bottom 2.54: 55.29,34.45 55.16,34.45 | 54.87,34.23 55.07,34.23 55.29,34.45 | 55.29,34.45 55.03,34.2 56.81,34.2 TP17.T@3
  Bottom 7.62: R50.CURRENT2 55.16,34.45 55.16,34.32 | 54.87,34.23 54.87,19.71
N$27  (via drill 0.51)
  Top 0.254: R54.2 70.57,83.3 v71.54,82.33
  Bottom 0.254: TP19.T@2 71.8,19.2 71.8,19.21 71.79,19.2 | TP19.T@3 71.8,34.2 71.9,34.09 | TP19.T@3 71.54,34.2 71.42,34.07 71.29,34.2 | 71.92,34.07 71.9,34.07 TP19.T@3
  Bottom 0.381: v71.54,82.33 71.92,81.95 71.92,34.07
  Bottom 2.54: TP19.T@1 71.79,19.2 | TP19.T@2 71.9,34.09 | 71.29,34.2 TP19.T@4
N$28
  Top 0.18: J12.CONDUCTOR 86.49,103.25 86.5,103.25 84.99,101.74 84.99,94.75 R69.1
  Bottom 0.18: R67.2 96.55,96.05 95.5,95 90,95 86.5,98.5 86.5,103.5 86.49,103.5 J12.CONDUCTOR
N$29
  Top 0.178: 82.45,89.95 C34.2 R71.2 82.95,92.49 83.97,91.47 84.86,91.47 84.99,91.35 R69.2 86.7,91.41 87.02,91.09 | 87.02,91.09 D12.C | 87.02,91.09 87.02,90.2 87.91,89.31 89.3,89.31 89.43,89.19 IC25.3
N$30  (via drill 0.51)
  Top 0.178: v86.51,84.62 IC23.1
  Bottom 0.381: R73.SENSE2 86.51,74.71 89.3,77.5 89.3,79.66 86.51,82.46 v86.51,84.62
N$31  (via drill 0.51)
  Top 0.178: v85.11,84.62 84.22,85.5 82.32,85.5 82.19,85.63 IC23.8
  Bottom 0.381: R73.SENSE1 86.51,81.44 85.11,82.84 v85.11,84.62
N$32
  Top 0.178: IC23.6 84.35,86.9 84.99,86.27 IC23.2
N$33
  Top 0.178: R75.2 91.32,86 91.34,86.01 | 89.43,90.33 89.3,90.46 IC25.2 89.43,90.46 89.3,90.33 90.7,90.33 91.34,89.7 91.34,86.01 | 91.34,86.01 C36.1 89.05,86.01 87.78,87.16 87.4,87.54 87.4,88.17 87.14,88.43 84.86,88.43 83.97,87.54 IC23.5 82.06,87.82 80.07,87.82 R90.1
N$34
  Top 0.178: 94.51,89.19 IC25.6 93.11,89.19 92.73,88.81 92.73,87.28 93.22,86.79 C36.2 93.11,86.01 93.18,85.95 R77.1
N$35
  Top 3.81: 81.81,34.2 TP24.T@3 | TP24.T@2 81.9,34.11 81.81,34.2 | TP24.T@4 78.1,34.32 78.13,34.32 78.1,34.3 TP24.T@4 | TP24.T@1 TP24.T@4 | TP24.T@4 78.1,34.07 78.13,34.07 78.25,34.2 81.81,34.2
  Top 7.62: R73.CURRENT2 80.16,34.32
  Bottom 2.54: 80.29,34.45 80.16,34.45 | 79.87,34.23 80.07,34.23 80.29,34.45 | 80.29,34.45 80.03,34.2 81.81,34.2 TP24.T@3
  Bottom 7.62: R73.CURRENT2 80.16,34.45 80.16,34.32 | 79.87,34.23 79.87,19.71
N$36  (via drill 0.51)
  Top 0.254: R77.2 95.57,83.3 v96.54,82.33
  Bottom 0.254: TP26.T@2 96.8,19.2 96.8,19.21 96.79,19.2 | TP26.T@3 96.8,34.2 96.9,34.09 | TP26.T@3 96.54,34.2 96.42,34.07 96.29,34.2 | 96.92,34.07 96.9,34.07 TP26.T@3
  Bottom 0.381: v96.54,82.33 96.92,81.95 96.92,34.07
  Bottom 2.54: TP26.T@1 96.79,19.2 | TP26.T@2 96.9,34.09 | 96.29,34.2 TP26.T@4
N$37
  Top 0.18: J10.CONDUCTOR 111.49,103.5 111.5,103.5 109.99,101.99 109.99,94.75 R57.1
  Bottom 0.18: R55.2 121.55,96.05 120.5,95 115,95 111.5,98.5 111.5,103.5 111.49,103.5 J10.CONDUCTOR
N$38
  Top 0.178: 107.45,89.95 C28.2 R59.2 107.95,92.49 108.97,91.47 109.86,91.47 109.99,91.35 R57.2 111.7,91.41 112.02,91.09 | 112.02,91.09 D10.C | 112.02,91.09 112.02,90.2 112.91,89.31 114.3,89.31 114.43,89.19 IC21.3
N$39  (via drill 0.51)
  Top 0.178: v111.51,84.62 IC19.1
  Bottom 0.381: R61.SENSE2 111.51,74.71 114.3,77.5 114.3,79.66 111.51,82.46 v111.51,84.62
N$40  (via drill 0.51)
  Top 0.178: v110.11,84.62 109.22,85.5 107.32,85.5 107.19,85.63 IC19.8
  Bottom 0.381: R61.SENSE1 111.51,81.44 110.11,82.84 v110.11,84.62
N$41
  Top 0.178: IC19.6 109.35,86.9 109.99,86.27 IC19.2
N$42
  Top 0.178: R63.2 116.32,86 116.34,86.01 | 114.43,90.33 114.3,90.46 IC21.2 114.43,90.46 114.3,90.33 115.7,90.33 116.34,89.7 116.34,86.01 | 116.34,86.01 C30.1 114.05,86.01 112.78,87.16 112.4,87.54 112.4,88.17 112.14,88.43 109.86,88.43 108.97,87.54 IC19.5 107.06,87.82 105.07,87.82 R89.1
N$43
  Top 0.178: 119.51,89.19 IC21.6 118.11,89.19 117.73,88.81 117.73,87.28 118.22,86.79 C30.2 118.11,86.01 118.18,85.95 R65.1
N$44
  Top 3.81: 106.81,34.2 TP20.T@3 | TP20.T@2 106.9,34.11 106.81,34.2 | TP20.T@4 103.1,34.32 103.13,34.32 103.1,34.3 TP20.T@4 | TP20.T@1 TP20.T@4 | TP20.T@4 103.1,34.07 103.13,34.07 103.25,34.2 106.81,34.2
  Top 7.62: R61.CURRENT2 105.16,34.32
  Bottom 2.54: 105.29,34.45 105.16,34.45 | 104.87,34.23 105.07,34.23 105.29,34.45 | 105.29,34.45 105.03,34.2 106.81,34.2 TP20.T@3
  Bottom 7.62: R61.CURRENT2 105.16,34.45 105.16,34.32 | 104.87,34.23 104.87,19.71
N$45  (via drill 0.51)
  Top 0.254: R65.2 120.57,83.3 v121.54,82.33
  Bottom 0.254: TP22.T@2 121.8,19.2 121.8,19.21 121.79,19.2 | TP22.T@3 121.8,34.2 121.9,34.09 | TP22.T@3 121.54,34.2 121.42,34.07 121.29,34.2 | 121.92,34.07 121.9,34.07 TP22.T@3 | 121.92,81.95 v121.54,82.33
  Bottom 0.381: 121.92,34.07 121.92,81.95
  Bottom 2.54: TP22.T@1 121.79,19.2 | TP22.T@2 121.9,34.09 | 121.29,34.2 TP22.T@4
N$46
  Top 0.18: J8.CONDUCTOR 136.49,103.5 136.5,103.5 134.99,101.99 134.99,94.75 R45.1
  Bottom 0.18: R43.2 146.55,96.05 145.5,95 140,95 136.5,98.5 136.5,103.5 136.49,103.5 J8.CONDUCTOR
N$47
  Top 0.178: 132.45,89.95 C22.2 R47.2 132.95,92.49 133.97,91.47 134.86,91.47 134.99,91.35 R45.2 136.7,91.41 137.02,91.09 | 137.02,91.09 D8.C | 137.02,91.09 137.02,90.2 137.91,89.31 139.3,89.31 139.43,89.19 IC17.3
N$48  (via drill 0.51)
  Top 0.178: v136.51,84.62 IC15.1
  Bottom 0.381: R49.SENSE2 136.51,74.71 139.3,77.5 139.3,79.66 136.51,82.46 v136.51,84.62
N$49  (via drill 0.51)
  Top 0.178: v135.11,84.62 134.22,85.5 132.32,85.5 132.19,85.63 IC15.8
  Bottom 0.381: R49.SENSE1 136.51,81.44 135.11,82.84 v135.11,84.62
N$50
  Top 0.178: IC15.6 134.35,86.9 134.99,86.27 IC15.2
N$51
  Top 0.178: R51.2 141.32,86 141.34,86.01 | 139.43,90.33 139.3,90.46 IC17.2 139.43,90.46 139.3,90.33 140.7,90.33 141.34,89.7 141.34,86.01 | 141.34,86.01 C24.1 139.05,86.01 137.78,87.16 137.4,87.54 137.4,88.17 137.15,88.43 134.86,88.43 133.97,87.54 IC15.5 132.06,87.82 130.07,87.82 R88.1
N$52
  Top 0.178: 144.51,89.19 IC17.6 143.11,89.19 142.73,88.81 142.73,87.28 143.22,86.79 C24.2 143.11,86.01 143.18,85.95 R53.1
N$53
  Top 3.81: 131.81,34.2 TP16.T@3 | TP16.T@2 131.9,34.11 131.81,34.2 | TP16.T@4 128.1,34.32 128.13,34.32 128.1,34.3 TP16.T@4 | TP16.T@1 TP16.T@4 | TP16.T@4 128.1,34.07 128.13,34.07 128.25,34.2 131.81,34.2
  Top 7.62: R49.CURRENT2 130.16,34.32
  Bottom 2.54: 130.29,34.45 130.16,34.45 | 129.87,34.23 130.07,34.23 130.29,34.45 | 130.29,34.45 130.03,34.2 131.81,34.2 TP16.T@3
  Bottom 7.62: R49.CURRENT2 130.16,34.45 130.16,34.32 | 129.87,34.23 129.87,19.71
N$54  (via drill 0.51)
  Top 0.254: R53.2 145.57,83.3 v146.54,82.33
  Bottom 0.254: TP18.T@2 146.8,19.2 146.8,19.21 146.79,19.2 | TP18.T@3 146.8,34.2 146.9,34.09 | TP18.T@3 146.54,34.2 146.42,34.07 146.29,34.2 | 146.92,34.07 146.9,34.07 TP18.T@3 | 146.92,81.95 v146.54,82.33
  Bottom 0.381: 146.92,34.07 146.92,81.95
  Bottom 2.54: TP18.T@1 146.79,19.2 | TP18.T@2 146.9,34.09 | 146.29,34.2 TP18.T@4
N$55
  Top 0.18: J3.CONDUCTOR 161.49,103.25 161.5,103.25 159.99,101.74 159.99,94.75 R6.1
  Bottom 0.18: R3.2 171.55,96.05 170.5,95 165,95 161.5,98.5 161.5,103.5 161.49,103.5 J3.CONDUCTOR
N$56
  Top 0.178: 157.45,89.95 C3.2 R9.2 157.95,92.49 158.97,91.47 159.86,91.47 159.99,91.35 R6.2 161.7,91.41 162.02,91.09 | 162.02,91.09 D3.C | 162.02,91.09 162.02,90.2 162.91,89.31 164.3,89.31 164.43,89.19 IC6.3
N$57  (via drill 0.51)
  Top 0.178: v161.51,84.62 IC3.1
  Bottom 0.381: R12.SENSE2 161.51,74.71 164.3,77.5 164.3,79.66 161.51,82.46 v161.51,84.62
N$58  (via drill 0.51)
  Top 0.178: v160.11,84.62 159.22,85.5 157.32,85.5 157.19,85.63 IC3.8
  Bottom 0.381: R12.SENSE1 161.51,81.44 160.11,82.84 v160.11,84.62
N$59
  Top 0.178: IC3.6 159.35,86.9 159.99,86.27 IC3.2
N$60
  Top 0.178: R15.2 166.32,86 166.34,86.01 | 164.43,90.33 164.3,90.46 IC6.2 164.43,90.46 164.3,90.33 165.7,90.33 166.34,89.7 166.34,86.01 | 166.34,86.01 C6.1 164.05,86.01 162.78,87.16 162.4,87.54 162.4,88.17 162.15,88.43 159.86,88.43 158.97,87.54 IC3.5 157.06,87.82 155.07,87.82 R87.1
N$61
  Top 0.178: 169.51,89.19 IC6.6 168.11,89.19 167.73,88.81 167.73,87.28 168.22,86.79 C6.2 168.11,86.01 168.18,85.95 R18.1
N$62
  Top 3.81: 156.81,34.2 TP3.T@3 | TP3.T@2 156.9,34.11 156.81,34.2 | TP3.T@4 153.1,34.32 153.13,34.32 153.1,34.3 TP3.T@4 | TP3.T@1 TP3.T@4 | TP3.T@4 153.1,34.07 153.13,34.07 153.25,34.2 156.81,34.2
  Top 7.62: R12.CURRENT2 155.16,34.32
  Bottom 2.54: 155.29,34.45 155.16,34.45 | 154.87,34.23 155.07,34.23 155.29,34.45 | 155.29,34.45 155.03,34.2 156.81,34.2 TP3.T@3
  Bottom 7.62: R12.CURRENT2 155.16,34.45 155.16,34.32 | 154.87,34.23 154.87,19.71
N$63  (via drill 0.51)
  Top 0.254: R18.2 170.57,83.3 v171.54,82.33
  Bottom 0.254: TP6.T@2 171.8,19.2 171.8,19.21 171.79,19.2 | TP6.T@3 171.8,34.2 171.9,34.09 | TP6.T@3 171.54,34.2 171.42,34.07 171.29,34.2 | 171.92,34.07 171.9,34.07 TP6.T@3
  Bottom 0.381: v171.54,82.33 171.92,81.95 171.92,34.07
  Bottom 2.54: 171.79,19.2 TP6.T@1 | 171.9,34.09 TP6.T@2 | 171.29,34.2 TP6.T@4
N$64
  Top 0.18: J7.CONDUCTOR 186.49,103.25 186.5,103.25 184.99,101.74 184.99,94.75 R34.1
  Bottom 0.18: R32.2 196.55,96.05 195.5,95 190,95 186.5,98.5 186.5,103 186.49,103 J7.CONDUCTOR
N$65
  Top 0.178: 182.45,89.95 C17.2 R36.2 182.95,92.49 183.97,91.47 184.86,91.47 184.99,91.35 R34.2 186.7,91.41 187.02,91.09 | 187.02,91.09 D7.C | 187.02,91.09 187.02,90.2 187.91,89.31 189.3,89.31 189.43,89.19 IC14.3
N$66  (via drill 0.51)
  Top 0.178: v186.51,84.62 IC12.1
  Bottom 0.381: R38.SENSE2 186.51,74.71 189.3,77.5 189.3,79.66 186.51,82.46 v186.51,84.62
N$67  (via drill 0.51)
  Top 0.178: v185.11,84.62 184.22,85.5 182.32,85.5 182.19,85.63 IC12.8
  Bottom 0.381: R38.SENSE1 186.51,81.44 185.11,82.84 v185.11,84.62
N$68
  Top 0.178: IC12.6 184.35,86.9 184.99,86.27 IC12.2
N$69
  Top 0.178: R40.2 191.32,86 191.34,86.01 | 189.43,90.33 189.3,90.46 IC14.2 189.43,90.46 189.3,90.33 190.7,90.33 191.34,89.7 191.34,86.01 | 191.34,86.01 C19.1 189.05,86.01 187.78,87.16 187.4,87.54 187.4,88.17 187.15,88.43 184.86,88.43 183.97,87.54 IC12.5 182.06,87.82 180.07,87.82 R86.1
N$70
  Top 0.178: 194.51,89.19 IC14.6 193.11,89.19 192.73,88.81 192.73,87.28 193.22,86.79 C19.2 193.11,86.01 193.18,85.95 R42.1
N$71
  Top 3.81: 181.81,34.2 TP13.T@3 | TP13.T@2 181.9,34.11 181.81,34.2 | TP13.T@4 178.1,34.32 178.13,34.32 178.1,34.3 TP13.T@4 | TP13.T@1 TP13.T@4 | TP13.T@4 178.1,34.07 178.13,34.07 178.25,34.2 181.81,34.2
  Top 7.62: R38.CURRENT2 180.16,34.32
  Bottom 2.54: 180.29,34.45 180.16,34.45 | 179.87,34.23 180.07,34.23 180.29,34.45 | 180.29,34.45 180.03,34.2 181.81,34.2 TP13.T@3
  Bottom 7.62: R38.CURRENT2 180.16,34.45 180.16,34.32 | 179.87,34.23 179.87,19.71
N$72  (via drill 0.51)
  Top 0.254: R42.2 195.57,83.3 v196.54,82.33
  Bottom 0.254: TP15.T@2 196.8,19.2 196.8,19.21 196.79,19.2 | TP15.T@3 196.8,34.2 196.9,34.09 | TP15.T@3 196.54,34.2 196.42,34.07 196.29,34.2 | 196.92,34.07 196.9,34.07 TP15.T@3
  Bottom 0.381: v196.54,82.33 196.92,81.95 196.92,34.07
  Bottom 2.54: 196.79,19.2 TP15.T@1 | 196.9,34.09 TP15.T@2 | 196.29,34.2 TP15.T@4
N$73
  Top 0.18: J5.CONDUCTOR 211.49,103.25 211.5,103.25 209.99,101.74 209.99,94.75 R22.1
  Bottom 0.18: R20.2 221.55,96.05 220.5,95 215,95 211.5,98.5 211.5,103.5 211.49,103.5 J5.CONDUCTOR
N$74
  Top 0.178: 207.45,89.95 C11.2 R24.2 207.95,92.49 208.97,91.47 209.86,91.47 209.99,91.35 R22.2 211.7,91.41 212.02,91.09 | 212.02,91.09 D5.C | 212.02,91.09 212.02,90.2 212.91,89.31 214.3,89.31 214.43,89.19 IC10.3
N$75  (via drill 0.51)
  Top 0.178: v211.51,84.62 IC8.1
  Bottom 0.381: R26.SENSE2 211.51,74.71 214.3,77.5 214.3,79.66 211.51,82.46 v211.51,84.62
N$76  (via drill 0.51)
  Top 0.178: v210.11,84.62 209.22,85.5 207.32,85.5 207.19,85.63 IC8.8
  Bottom 0.381: R26.SENSE1 211.51,81.44 210.11,82.84 v210.11,84.62
N$77
  Top 0.178: IC8.6 209.35,86.9 209.99,86.27 IC8.2
N$78
  Top 0.178: R28.2 216.32,86 216.34,86.01 | 214.43,90.33 214.3,90.46 IC10.2 214.43,90.46 214.3,90.33 215.7,90.33 216.34,89.7 216.34,86.01 | 216.34,86.01 C13.1 214.05,86.01 212.78,87.16 212.4,87.54 212.4,88.17 212.15,88.43 209.86,88.43 208.97,87.54 IC8.5 207.06,87.82 205.07,87.82 R85.1
N$79
  Top 0.178: 219.51,89.19 IC10.6 218.11,89.19 217.73,88.81 217.73,87.28 218.22,86.79 C13.2 218.11,86.01 218.18,85.95 R30.1
N$80
  Top 3.81: 206.81,34.2 TP9.T@3 | TP9.T@2 206.9,34.11 206.81,34.2 | TP9.T@4 203.1,34.32 203.13,34.32 203.1,34.3 TP9.T@4 | TP9.T@4 TP9.T@1 | TP9.T@4 203.1,34.07 203.13,34.07 203.25,34.2 206.81,34.2
  Top 7.62: R26.CURRENT2 205.16,34.32
  Bottom 2.54: 205.16,34.45 205.29,34.45 | 204.87,34.23 205.07,34.23 205.29,34.45 | 205.29,34.45 205.03,34.2 206.81,34.2 TP9.T@3
  Bottom 7.62: R26.CURRENT2 205.16,34.45 205.16,34.32 | 204.87,34.23 204.87,19.71
N$81  (via drill 0.51)
  Top 0.254: R30.2 220.57,83.3 v221.54,82.33
  Bottom 0.254: TP11.T@2 221.8,19.2 221.8,19.21 221.79,19.2 | TP11.T@3 221.8,34.2 221.9,34.09 | TP11.T@3 221.54,34.2 221.42,34.07 221.29,34.2 | 221.92,34.07 221.9,34.07 TP11.T@3
  Bottom 0.381: v221.54,82.33 221.92,81.95 221.92,34.07
  Bottom 2.54: 221.79,19.2 TP11.T@1 | 221.9,34.09 TP11.T@2 | 221.29,34.2 TP11.T@4
N$82
  Top 0.18: J2.CONDUCTOR 236.49,103.25 236.5,103.25 234.99,101.74 234.99,94.75 R5.1
  Bottom 0.18: R2.2 246.55,96.05 245.5,95 240,95 236.5,98.5 236.5,103.5 236.49,103.5 J2.CONDUCTOR
N$83
  Top 0.178: 232.45,89.95 C2.2 R8.2 232.95,92.49 233.97,91.47 234.86,91.47 234.99,91.35 R5.2 236.7,91.41 237.02,91.09 | 237.02,91.09 D2.C | 237.02,91.09 237.02,90.2 237.91,89.31 239.3,89.31 239.43,89.19 IC5.3
N$84  (via drill 0.51)
  Top 0.178: v236.51,84.62 IC2.1
  Bottom 0.381: R11.SENSE2 236.51,74.71 239.3,77.5 239.3,79.66 236.51,82.46 v236.51,84.62
N$85  (via drill 0.51)
  Top 0.178: v235.11,84.62 234.22,85.5 232.32,85.5 232.19,85.63 IC2.8
  Bottom 0.381: R11.SENSE1 236.51,81.44 235.11,82.84 v235.11,84.62
N$86
  Top 0.178: IC2.6 234.35,86.9 234.99,86.27 IC2.2
N$87
  Top 0.178: R14.2 241.32,86 241.34,86.01 | 239.43,90.33 239.3,90.46 IC5.2 239.43,90.46 239.3,90.33 240.7,90.33 241.34,89.7 241.34,86.01 | 241.34,86.01 C5.1 239.05,86.01 237.78,87.16 237.4,87.54 237.4,88.17 237.15,88.43 234.86,88.43 233.97,87.54 IC2.5 232.06,87.82 230.07,87.82 R84.1
N$88
  Top 0.178: 244.51,89.19 IC5.6 243.11,89.19 242.73,88.81 242.73,87.28 243.22,86.79 C5.2 243.11,86.01 243.18,85.95 R17.1
N$89
  Top 3.81: 231.81,34.2 TP2.T@3 | TP2.T@2 231.9,34.11 231.81,34.2 | TP2.T@4 228.1,34.32 228.13,34.32 228.1,34.3 TP2.T@4 | TP2.T@4 TP2.T@1 | TP2.T@4 228.1,34.07 228.13,34.07 228.25,34.2 231.81,34.2
  Top 7.62: R11.CURRENT2 230.16,34.32
  Bottom 2.54: 230.29,34.45 230.16,34.45 | 229.87,34.23 230.07,34.23 230.29,34.45 | 230.29,34.45 230.03,34.2 231.81,34.2 TP2.T@3
  Bottom 7.62: R11.CURRENT2 230.16,34.45 230.16,34.32 | 229.87,34.23 229.87,19.71
N$90  (via drill 0.51)
  Top 0.254: R17.2 245.57,83.3 v246.54,82.33
  Bottom 0.254: TP5.T@2 246.8,19.2 246.8,19.21 246.79,19.2 | TP5.T@3 246.8,34.2 246.9,34.09 | TP5.T@3 246.54,34.2 246.42,34.07 246.29,34.2 | 246.92,34.07 246.9,34.07 TP5.T@3
  Bottom 0.381: v246.54,82.33 246.92,81.95 246.92,34.07
  Bottom 2.54: TP5.T@1 246.79,19.2 | TP5.T@2 246.9,34.09 | 246.29,34.2 TP5.T@4
N$91
  Top 0.18: J6.CONDUCTOR 261.49,103.25 261.5,103.25 259.99,101.74 259.99,94.75 R33.1
  Bottom 0.18: R31.2 271.55,96.05 270.5,95 265,95 261.5,98.5 261.5,103.5 261.49,103.5 J6.CONDUCTOR
N$92
  Top 0.178: 257.45,89.95 C16.2 R35.2 257.95,92.49 258.97,91.47 259.86,91.47 259.99,91.35 R33.2 261.7,91.41 262.02,91.09 | 262.02,91.09 D6.C | 262.02,91.09 262.02,90.2 262.91,89.31 264.3,89.31 264.43,89.19 IC13.3
N$93  (via drill 0.51)
  Top 0.178: v261.51,84.62 IC11.1
  Bottom 0.381: R37.SENSE2 261.51,74.71 264.3,77.5 264.3,79.66 261.51,82.46 v261.51,84.62
N$94  (via drill 0.51)
  Top 0.178: v260.11,84.62 259.22,85.5 257.32,85.5 257.19,85.63 IC11.8
  Bottom 0.381: R37.SENSE1 261.51,81.44 260.11,82.84 v260.11,84.62
N$95
  Top 0.178: IC11.6 259.35,86.9 259.99,86.27 IC11.2
N$96
  Top 0.178: R39.2 266.32,86 266.34,86.01 | 264.43,90.33 264.3,90.46 IC13.2 264.43,90.46 264.3,90.33 265.7,90.33 266.34,89.7 266.34,86.01 | 266.34,86.01 C18.1 264.05,86.01 262.78,87.16 262.4,87.54 262.4,88.17 262.14,88.43 259.86,88.43 258.97,87.54 IC11.5 257.06,87.82 255.07,87.82 R83.1
N$97
  Top 0.178: 269.51,89.19 IC13.6 268.11,89.19 267.73,88.81 267.73,87.28 268.22,86.79 C18.2 268.11,86.01 268.18,85.95 R41.1
N$98
  Top 3.81: 256.81,34.2 TP12.T@3 | TP12.T@2 256.9,34.11 256.81,34.2 | TP12.T@4 253.1,34.32 253.13,34.32 253.1,34.3 TP12.T@4 | TP12.T@1 TP12.T@4 | TP12.T@4 253.1,34.07 253.13,34.07 253.25,34.2 256.81,34.2
  Top 7.62: R37.CURRENT2 255.16,34.32
  Bottom 2.54: 255.29,34.45 255.16,34.45 | 254.87,34.23 255.07,34.23 255.29,34.45 | 255.29,34.45 255.03,34.2 256.81,34.2 TP12.T@3
  Bottom 7.62: R37.CURRENT2 255.16,34.45 255.16,34.32 | 254.87,34.23 254.87,19.71
N$99  (via drill 0.51)
  Top 0.254: R41.2 270.57,83.3 v271.54,82.33
  Bottom 0.254: TP14.T@2 271.8,19.2 271.8,19.21 271.79,19.2 | TP14.T@3 271.8,34.2 271.9,34.09 | TP14.T@3 271.54,34.2 271.42,34.2 271.29,34.2 | 271.92,34.07 271.9,34.07 TP14.T@3
  Bottom 0.381: v271.54,82.33 271.92,81.95 271.92,34.07
  Bottom 2.54: TP14.T@1 271.79,19.2 | TP14.T@2 271.9,34.09 | 271.29,34.2 TP14.T@4
N$100
  Top 0.18: J4.CONDUCTOR 286.49,103.25 286.5,103.25 284.99,101.74 284.99,94.75 R21.1
  Bottom 0.18: R19.2 296.55,96.05 295.5,95 290,95 286.5,98.5 286.5,103.5 286.49,103.5 J4.CONDUCTOR
N$101
  Top 0.178: 282.45,89.95 C10.2 R23.2 282.95,92.49 283.97,91.47 284.86,91.47 284.99,91.35 R21.2 286.7,91.41 287.02,91.09 | 287.02,91.09 D4.C | 287.02,91.09 287.02,90.2 287.91,89.31 289.3,89.31 289.43,89.19 IC9.3
N$102  (via drill 0.51)
  Top 0.178: v286.51,84.62 IC7.1
  Bottom 0.381: R25.SENSE2 286.51,74.71 289.3,77.5 289.3,79.66 286.51,82.46 v286.51,84.62
N$103  (via drill 0.51)
  Top 0.178: v285.11,84.62 284.22,85.5 282.32,85.5 282.19,85.63 IC7.8
  Bottom 0.381: R25.SENSE1 286.51,81.44 285.11,82.84 v285.11,84.62
N$104
  Top 0.178: IC7.6 284.35,86.9 284.99,86.27 IC7.2
N$105
  Top 0.178: R27.2 291.32,86 291.34,86.01 | 289.43,90.33 289.3,90.46 IC9.2 289.43,90.46 289.3,90.33 290.7,90.33 291.34,89.7 291.34,86.01 | 291.34,86.01 C12.1 289.05,86.01 287.78,87.16 287.4,87.54 287.4,88.17 287.14,88.43 284.86,88.43 283.97,87.54 IC7.5 282.06,87.82 280.07,87.82 | 280.07,87.82 280.04,87.82 | R82.1 280.07,87.82
N$106
  Top 0.178: 294.51,89.19 IC9.6 293.11,89.19 292.73,88.81 292.73,87.28 293.22,86.79 C12.2 293.11,86.01 293.18,85.95 R29.1
N$107
  Top 3.81: 281.81,34.2 TP8.T@3 | TP8.T@2 281.9,34.11 281.81,34.2 | TP8.T@4 278.1,34.32 278.13,34.32 278.1,34.3 TP8.T@4 | TP8.T@1 TP8.T@4 | TP8.T@4 278.1,34.07 278.13,34.07 278.25,34.2 281.81,34.2
  Top 7.62: R25.CURRENT2 280.16,34.32
  Bottom 2.54: 280.29,34.45 280.16,34.45 | 279.87,34.23 280.07,34.23 280.29,34.45 | 280.29,34.45 280.03,34.2 281.81,34.2 TP8.T@3
  Bottom 7.62: R25.CURRENT2 280.16,34.45 280.16,34.32 | 279.87,34.23 279.87,19.71
N$108  (via drill 0.51)
  Top 0.254: R29.2 295.57,83.3 v296.54,82.33
  Bottom 0.254: TP10.T@2 296.8,19.2 296.8,19.21 296.79,19.2 | TP10.T@3 296.8,34.2 296.9,34.09 | TP10.T@3 296.54,34.2 296.42,34.2 296.29,34.2 | 296.92,34.07 296.9,34.07 TP10.T@3
  Bottom 0.381: v296.54,82.33 296.92,81.95 296.92,34.07
  Bottom 2.54: TP10.T@1 296.79,19.2 | TP10.T@2 296.9,34.09 | 296.29,34.2 TP10.T@4
N$109
  Top 0.18: J1.CONDUCTOR 311.49,103.25 311.5,103.25 309.99,101.74 309.99,94.75 R4.1
  Bottom 0.18: R1.2 322,96 321.5,96 320.5,95 315,95 311.5,98.5 311.5,103.5 311.49,103.5 J1.CONDUCTOR
N$110
  Top 0.178: 307.45,89.95 C1.2 R7.2 307.95,92.49 308.97,91.47 309.86,91.47 309.99,91.35 R4.2 311.7,91.41 312.02,91.09 | 312.02,91.09 D1.C | 312.02,91.09 312.02,90.2 312.91,89.31 314.3,89.31 314.43,89.19 IC4.3
N$111  (via drill 0.51)
  Top 0.178: v311.51,84.62 IC1.1
  Bottom 0.381: R10.SENSE2 311.51,74.71 314.3,77.5 314.3,79.66 311.51,82.46 v311.51,84.62
N$112  (via drill 0.51)
  Top 0.178: v310.11,84.62 309.22,85.5 307.32,85.5 307.19,85.63 IC1.8
  Bottom 0.381: R10.SENSE1 311.51,81.44 310.11,82.84 v310.11,84.62
N$113
  Top 0.178: IC1.6 309.35,86.9 309.99,86.27 IC1.2
N$114
  Top 0.178: R13.2 316.32,86 316.34,86.01 | 314.43,90.33 314.3,90.46 IC4.2 314.43,90.46 314.3,90.33 315.7,90.33 316.34,89.7 316.34,86.01 | 316.34,86.01 C4.1 314.05,86.01 312.78,87.16 312.4,87.54 312.4,88.17 312.14,88.43 309.86,88.43 308.97,87.54 IC1.5 307.06,87.82 305.07,87.82 | 305.07,87.82 304.93,87.82 | R81.1 305.07,87.82
N$115
  Top 0.178: 319.51,89.19 IC4.6 318.11,89.19 317.73,88.81 317.73,87.28 318.22,86.79 C4.2 318.11,86.01 318.18,85.95 R16.1
N$116
  Top 3.81: 306.81,34.2 TP1.T@3 | TP1.T@2 306.9,34.11 306.81,34.2 | TP1.T@4 303.1,34.32 303.13,34.32 303.1,34.3 TP1.T@4 | TP1.T@1 TP1.T@4 | TP1.T@4 303.1,34.07 303.13,34.07 303.25,34.2 306.81,34.2
  Top 7.62: R10.CURRENT2 305.16,34.32
  Bottom 2.54: 305.29,34.45 305.16,34.45 | 304.87,34.23 305.07,34.23 305.29,34.45 | 305.29,34.45 305.03,34.2 306.81,34.2 TP1.T@3
  Bottom 7.62: R10.CURRENT2 305.16,34.45 305.16,34.32 | 304.87,34.23 304.87,19.71
N$117  (via drill 0.51)
  Top 0.254: R16.2 320.57,83.3 v321.54,82.33
  Bottom 0.254: TP4.T@2 321.8,19.2 321.8,19.21 321.79,19.2 | TP4.T@3 321.8,34.2 321.9,34.09 | TP4.T@3 321.54,34.2 321.42,34.2 321.29,34.2 | 321.92,34.07 321.9,34.07 TP4.T@3
  Bottom 0.381: v321.54,82.33 321.92,81.95 321.92,34.07
  Bottom 2.54: TP4.T@1 321.79,19.2 | TP4.T@2 321.9,34.09 | 321.29,34.2 TP4.T@4
N$118
  Top 1: 325,1 325,12
N$119
  Top 1: 300,1 300,12
N$120
  Top 1: 250,12 250,1
N$121
  Top 1: 275,1 275,12
N$122
  Top 1: 225,1 225,12
N$123
  Top 1: 200,1 200,12
N$124
  Top 1: 175,1 175,12
N$125
  Top 1: 150,1 150,12
N$126
  Top 1: 125,1 125,12
N$127
  Top 1: 100,1 100,12
N$128
  Top 1: 75,1 75,12
N$129
  Top 1: 50,1 50,12
N$130
  Top 1: 25,1 25,12
N$131
  Bottom 0.18: R19.1 297,98 296.9,98.1 D16.A
N$132
  Bottom 0.18: R31.1 272,98 271.9,98.1 D17.A
N$133
  Bottom 0.18: R2.1 247,98 246.9,98.1 D18.A
N$134
  Bottom 0.18: R20.1 222,98 221.9,98.1 D20.A
N$135
  Bottom 0.18: R1.1 322,98 321.9,98.1 D15.A
N$136
  Bottom 0.18: R32.1 197,98 196.9,98.1 D21.A
N$137
  Bottom 0.18: R3.1 172,98 171.9,98.1 D19.A
N$138
  Bottom 0.18: R43.1 147,98 146.9,98.1 D22.A
N$139
  Bottom 0.18: R44.1 72,98 71.9,98.1 D23.A
N$140
  Bottom 0.18: R56.1 47,98 46.9,98.1 D25.A
N$141
  Bottom 0.18: R55.1 122,98 121.9,98.1 D24.A
N$142
  Bottom 0.18: R67.1 97,98 96.9,98.1 D27.A
N$143
  Bottom 0.18: R68.1 22,98 21.9,98.1 D26.A
N$144
  Bottom 0.36: +SUPPLY.TP 347.25,74.25 349,72.5 349,68.9 349.2,68.7 349.25,68.8 F1.1A
N$145  (via drill 0.71)
  Top 0.381: C40.2 IC27.3
  Top 0.4: C40.2 344.2,89.6 v344.2,86.3
  Bottom 0.4: F1.2A D14.2 | D14.2 329,76.4 | D14.2 328.93,73.8 344.2,73.8 v344.2,86.3
N$146
  Top 0.178: C42.2 336.49,91.95 336.49,93.92 R80.2 337.44,92.9 IC27.1 339.53,92.65 339.53,90.11 R79.1

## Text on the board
Top: CATS - Unipolar Rev:A1 | Cold Atoms Transfer System | J. Thywissen Labs | University of Toronto - Physics | 13 | 12 | 11 | 10 | 9 | 8 | 7 | 6 | 5 | 4 | 3 | 2 | 1 | Com
tDocu: CATS - Unipolar | Cold Atoms Transfer System | A1 | 0.007"(0.178mm) | 0.3"(7.62mm) | 0.007"(0.178mm) | n/a | n/a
